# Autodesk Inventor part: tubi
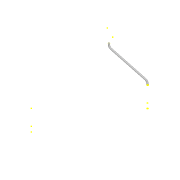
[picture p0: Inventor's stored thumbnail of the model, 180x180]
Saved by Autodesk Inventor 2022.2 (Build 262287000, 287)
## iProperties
Created: 2025-02
Part Number: tubi
Material: Rame
Document SubType Name: Modeling
Designer: 18907419
Density: 8.94 g/cm^3
Appearance: Rame - Satinato
Author: 18907419
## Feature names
1. Sweep1
2. Sweep2
3. Sweep3
4. Sweep4
5. Sweep5
## Parameters: d0 = 25 mm, d1 = 25 mm, d4 = 0, d5 = 0, d6 = 0, d7 = 0, d8 = 25 mm, d9 = 25 mm, d15 = 0, d16 = 0, d22 = 0, d23 = 0, d33 = 0, d34 = 0
